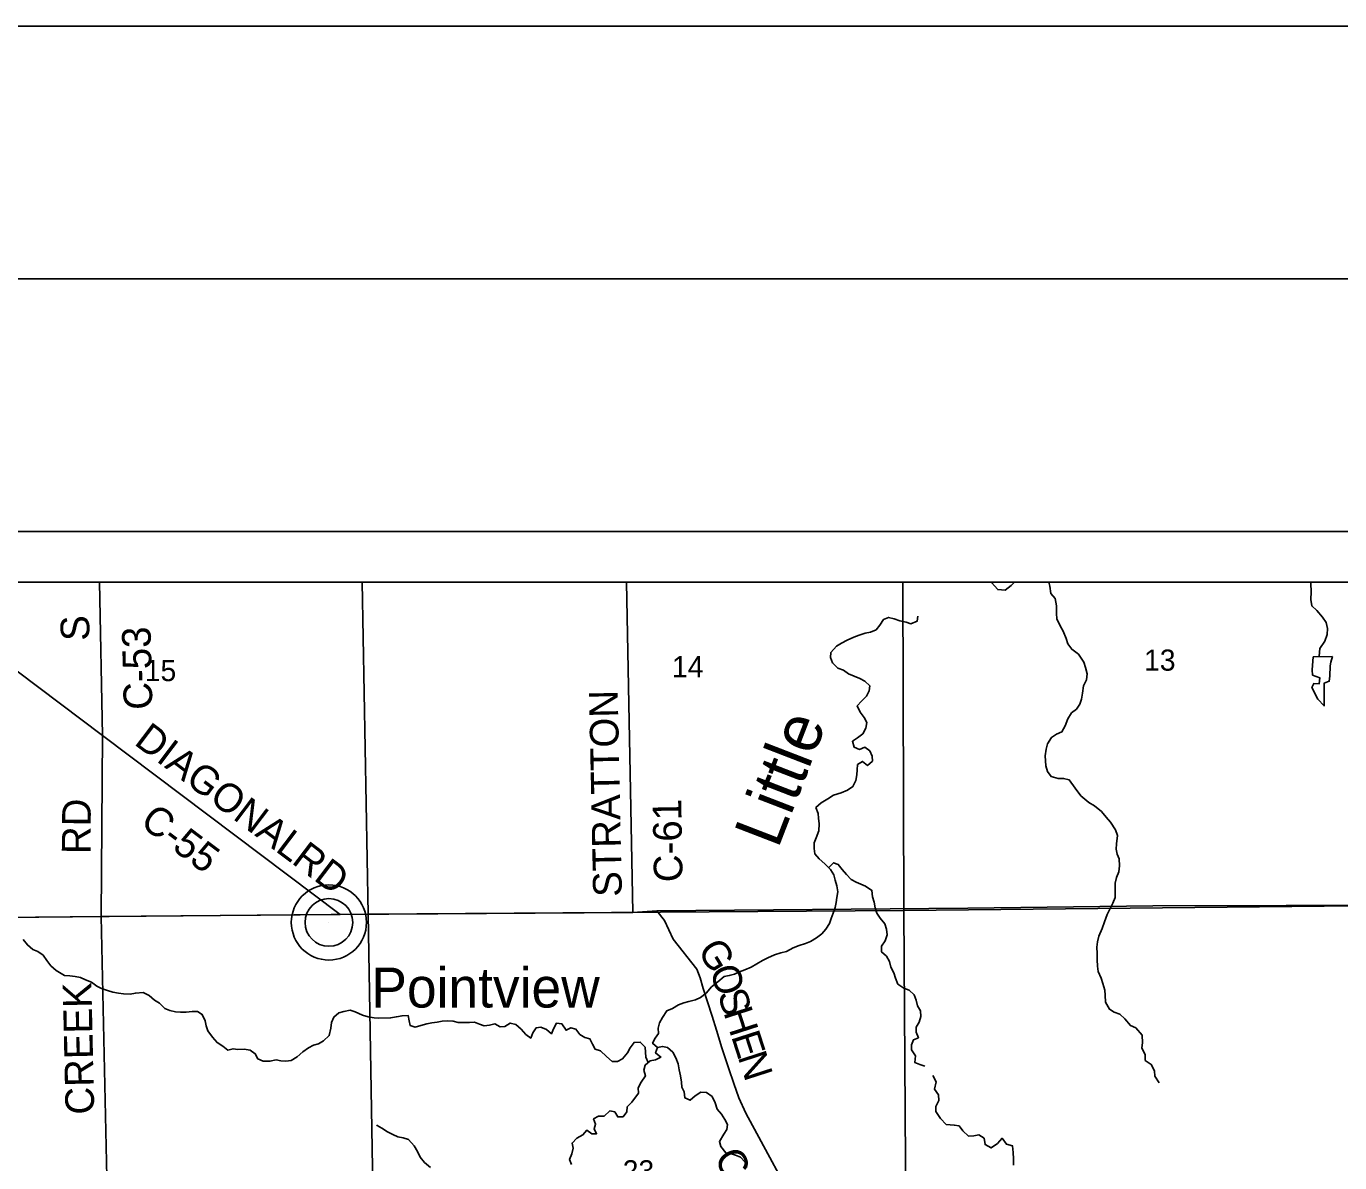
# Model space of a CAD drawing. Extents: x 0 to 34, y 0 to 22.
# Drawn here: x 2.754 to 5.353, y 19.751 to 22 of the extents above; entities that cross this region are included whole.
import ezdxf

# ---------------------------------------------------------------- set-up
doc = ezdxf.new("R2010")
doc.units = 0
for name, color, linetype in [('GM_X_County_Road', 7, 'Continuous'), ('GM_X_County_Road_Text', 7, 'Continuous'), ('GM_X_Minor_Lake', 7, 'Continuous'), ('GM_X_Minor_River', 7, 'Continuous'), ('GM_X_Minor_River_Text', 7, 'Continuous'), ('GM_X_Rail_Line', 7, 'Continuous'), ('GM_X_Section', 7, 'Continuous'), ('GM_X_Section_Text', 7, 'Continuous'), ('GM_X_State_Route', 7, 'Continuous'), ('GM_X_State_Shield', 7, 'Continuous'), ('GM_X_Township_Road', 7, 'Continuous'), ('GM_X_Township_Road_Text', 7, 'Continuous'), ('GM_X_Unincorporated', 7, 'Continuous'), ('GM_X_Unincorporated_Location', 7, 'Continuous'), ('GM_X_Unincorporated_Text', 7, 'Continuous'), ('SH_Border', 7, 'Continuous'), ('SH_Cut_Line', 7, 'Continuous'), ('SH_Data', 7, 'Continuous')]:
    doc.layers.add(name, color=color, linetype=linetype)

msp = doc.modelspace()

# ---------------------------------------------------------------- linework, layer by layer
at = {"layer": 'GM_X_County_Road'}
for p, q in [((2.9045, 20.5966), (2.8984, 20.9)), ((3.9542, 20.2462), (3.9417, 20.9)), ((2.9045, 20.5966), (3.3745, 20.2419)), ((4.0013, 20.2492), (3.9542, 20.2462))]:
    msp.add_line(p, q, dxfattribs=at)
msp.add_lwpolyline([(4.497, 19.2526), (4.4208, 19.3901), (4.2904, 19.6406), (4.1777, 19.8488), (4.1636, 19.8791), (4.1541, 19.9074), (4.1442, 19.9366), (4.1303, 19.9782), (4.1198, 20.013), (4.1112, 20.041), (4.093, 20.0955), (4.0874, 20.1167), (4.0803, 20.1337), (4.0339, 20.1931), (4.0167, 20.23), (4.0013, 20.2492)], dxfattribs=at)
at = {"layer": 'GM_X_Minor_Lake'}
for points in [[(5.3001, 20.7517), (5.2982, 20.7263), (5.2991, 20.716), (5.3137, 20.7102), (5.3123, 20.6988), (5.3013, 20.699), (5.2976, 20.6913), (5.3094, 20.6683), (5.3218, 20.6548), (5.3222, 20.7001), (5.332, 20.7036), (5.3333, 20.7135), (5.3338, 20.7341), (5.3355, 20.7417), (5.3388, 20.7524)], [(5.3388, 20.7524), (5.3001, 20.7517)]]:
    msp.add_lwpolyline(points, dxfattribs=at)
at = {"layer": 'GM_X_Minor_River'}
msp.add_line((3.4507, 20.9), (3.4509, 20.8992), dxfattribs=at)
for points in [[(4.7095, 20.9), (4.7025, 20.8932), (4.6905, 20.8842), (4.676, 20.8851), (4.6636, 20.899), (4.662, 20.9)], [(4.7773, 20.9), (4.7788, 20.8921), (4.7809, 20.8774), (4.7898, 20.8673), (4.7923, 20.8532), (4.7922, 20.838), (4.7931, 20.8274), (4.7995, 20.8135), (4.8053, 20.8029), (4.8116, 20.7886), (4.8148, 20.778), (4.8226, 20.7671), (4.8361, 20.7571), (4.8466, 20.7417), (4.8498, 20.7307), (4.8527, 20.7182), (4.8517, 20.7068), (4.8455, 20.6949), (4.8438, 20.6801), (4.8421, 20.6683), (4.8385, 20.6584), (4.8318, 20.6487), (4.8221, 20.641), (4.815, 20.6291), (4.8096, 20.6157), (4.8029, 20.6038), (4.7924, 20.5987), (4.7826, 20.5925), (4.7745, 20.5798), (4.7716, 20.5695), (4.7696, 20.5558), (4.7705, 20.5463), (4.7714, 20.5361), (4.7743, 20.5251), (4.7816, 20.5153), (4.7957, 20.511), (4.8064, 20.5112), (4.8174, 20.5083), (4.8291, 20.4922), (4.8403, 20.4772), (4.8565, 20.4634), (4.8676, 20.4571), (4.8811, 20.4459), (4.8904, 20.4347), (4.8989, 20.4246), (4.9094, 20.4099), (4.913, 20.3982), (4.911, 20.3818), (4.9104, 20.3716), (4.9125, 20.3617), (4.9161, 20.3519), (4.9167, 20.3382), (4.9154, 20.3268), (4.911, 20.3153), (4.9085, 20.3039), (4.9083, 20.2929), (4.9086, 20.2758), (4.9039, 20.2647), (4.8976, 20.2528), (4.8925, 20.2417), (4.8874, 20.2272), (4.8827, 20.2146), (4.8761, 20.1993), (4.8732, 20.1882), (4.8719, 20.1772), (4.8725, 20.165), (4.8727, 20.1525), (4.8733, 20.14), (4.875, 20.1293), (4.8809, 20.1158), (4.8841, 20.1056), (4.8881, 20.0923), (4.8887, 20.0825), (4.8893, 20.0688), (4.8971, 20.0545), (4.9067, 20.0489), (4.9174, 20.0449), (4.9274, 20.0356), (4.9386, 20.0225), (4.949, 20.0177), (4.9617, 20.0031), (4.9624, 19.9883), (4.961, 19.9784), (4.9681, 19.9645), (4.9675, 19.9534), (4.9798, 19.9453), (4.9861, 19.9325), (4.987, 19.9218), (4.9952, 19.9087)], [(5.295, 20.9), (5.2957, 20.8972), (5.296, 20.8808), (5.2955, 20.8656), (5.2976, 20.8527), (5.3076, 20.8434), (5.3189, 20.8307), (5.3259, 20.8198), (5.3284, 20.808), (5.3278, 20.7963), (5.3231, 20.7833), (5.3134, 20.7683), (5.3122, 20.7531), (5.3123, 20.7519)], [(4.518, 20.8328), (4.5165, 20.8225), (4.5041, 20.8175), (4.4946, 20.8208), (4.4825, 20.823), (4.4714, 20.8274), (4.4601, 20.83), (4.4499, 20.8261), (4.4428, 20.815), (4.4353, 20.8055), (4.4244, 20.8005), (4.4138, 20.7989), (4.4021, 20.795), (4.3911, 20.7907), (4.3779, 20.7849), (4.367, 20.7791), (4.3572, 20.7729), (4.346, 20.7607), (4.3449, 20.7504), (4.3488, 20.7402), (4.3595, 20.7293), (4.3709, 20.7256), (4.3808, 20.7184), (4.3918, 20.714), (4.4032, 20.7091), (4.4131, 20.7039), (4.4227, 20.6949), (4.4213, 20.685), (4.4164, 20.6743), (4.4067, 20.6644), (4.3981, 20.6548), (4.4035, 20.6427), (4.4115, 20.6317), (4.4169, 20.6219), (4.4151, 20.6105), (4.4092, 20.5998), (4.3986, 20.5918), (4.3885, 20.5848), (4.392, 20.5731), (4.4023, 20.5686), (4.4132, 20.5729), (4.4231, 20.5658), (4.4278, 20.5556), (4.4282, 20.5457), (4.4185, 20.5372), (4.4082, 20.5451), (4.3984, 20.5386), (4.3981, 20.5283), (4.3974, 20.5185), (4.3953, 20.507), (4.3893, 20.4952), (4.3788, 20.4879), (4.366, 20.4825), (4.3509, 20.4782), (4.3396, 20.4709), (4.3268, 20.4632), (4.3163, 20.4536), (4.3205, 20.4418), (4.3214, 20.4324), (4.3226, 20.4214), (4.322, 20.4077), (4.3168, 20.394), (4.3127, 20.384), (4.3128, 20.3727), (4.3141, 20.362), (4.3229, 20.3519), (4.3339, 20.3425), (4.3454, 20.3312), (4.3519, 20.3206), (4.3543, 20.3103), (4.3574, 20.299), (4.3594, 20.2868), (4.3573, 20.2754), (4.3562, 20.2659), (4.3544, 20.2557), (4.3504, 20.2446), (4.3467, 20.2343), (4.3434, 20.2244), (4.3359, 20.2133), (4.3277, 20.2038), (4.3175, 20.1957), (4.3058, 20.1884), (4.2957, 20.1845), (4.2828, 20.1806), (4.2715, 20.1759), (4.2579, 20.169), (4.247, 20.1659), (4.2345, 20.162), (4.2213, 20.1565), (4.2104, 20.1511), (4.1995, 20.1442), (4.1878, 20.138), (4.1754, 20.1326), (4.1652, 20.1283), (4.1554, 20.1241), (4.1448, 20.1213), (4.1346, 20.1193), (4.1218, 20.109), (4.1098, 20.0986), (4.0989, 20.0864), (4.0877, 20.0779)], [(4.3416, 20.3349), (4.351, 20.3445), (4.3605, 20.3412), (4.3685, 20.331), (4.3765, 20.3212), (4.3857, 20.311), (4.3956, 20.3061), (4.4051, 20.302), (4.4146, 20.2983), (4.4272, 20.2897), (4.4281, 20.2772), (4.4316, 20.2666), (4.4336, 20.2552), (4.4367, 20.2446), (4.4432, 20.2348), (4.4524, 20.2238), (4.4559, 20.2128), (4.4575, 20.2018), (4.4531, 20.1897), (4.446, 20.1793), (4.4461, 20.1679), (4.4556, 20.1597), (4.4618, 20.1487), (4.4646, 20.1377), (4.4707, 20.1268), (4.4735, 20.1161), (4.4785, 20.1044), (4.4899, 20.0962), (4.5009, 20.0925), (4.5109, 20.083), (4.5148, 20.0724), (4.5171, 20.0614), (4.5233, 20.0516), (4.5238, 20.0402), (4.5208, 20.0292), (4.5149, 20.0189), (4.5146, 20.0094), (4.5192, 19.998), (4.5094, 19.9942), (4.5054, 19.9839), (4.5055, 19.974), (4.5135, 19.9623), (4.5121, 19.949), (4.522, 19.9449), (4.5315, 19.9419)], [(3.0377, 20.0518), (3.0275, 20.0559), (3.0175, 20.0664), (3.0072, 20.0724), (2.9966, 20.0818), (2.9848, 20.0874), (2.9696, 20.0865), (2.959, 20.0845), (2.9458, 20.0852), (2.9363, 20.0866), (2.9246, 20.088), (2.9143, 20.0914), (2.9025, 20.0958), (2.893, 20.1003), (2.8827, 20.1078), (2.871, 20.113), (2.8611, 20.1171), (2.8504, 20.1193), (2.8398, 20.1204), (2.8292, 20.1214), (2.8125, 20.1315), (2.8022, 20.1402), (2.7941, 20.1507), (2.7868, 20.1613), (2.7765, 20.1688), (2.7667, 20.1725), (2.756, 20.1819), (2.7476, 20.1925)], [(4.0877, 20.0779), (4.0779, 20.0729), (4.065, 20.0701), (4.0548, 20.067), (4.0443, 20.0631), (4.0326, 20.0562), (4.0209, 20.0511), (4.0127, 20.0385), (4.0064, 20.0278), (4.0038, 20.0168), (4.0047, 20.0065), (3.9979, 19.997), (3.9931, 19.9871), (4.0027, 19.9788), (4.0125, 19.9808), (4.0223, 19.9786), (4.033, 19.9696), (4.0392, 19.9586), (4.0435, 19.9465), (4.0458, 19.9347), (4.0482, 19.9226), (4.0502, 19.9105), (4.0507, 19.9006), (4.0553, 19.8908), (4.057, 19.879), (4.0672, 19.8745), (4.0774, 19.883), (4.0883, 19.8907), (4.1, 19.89), (4.1107, 19.8817), (4.1169, 19.8693), (4.1211, 19.8568), (4.1292, 19.8469), (4.1357, 19.8364), (4.1415, 19.8265), (4.1401, 19.8167), (4.1341, 19.8071), (4.1252, 19.7926), (4.1279, 19.7827), (4.1379, 19.7703), (4.1473, 19.7692), (4.1568, 19.7659), (4.1671, 19.7618), (4.1759, 19.7516), (4.1798, 19.7414)], [(3.9841, 19.9491), (3.9794, 19.9596), (3.9784, 19.9794), (3.9685, 19.9895), (3.9564, 19.989), (3.9489, 19.9783), (3.9433, 19.9684), (3.9332, 19.9566), (3.9234, 19.9508), (3.9132, 19.9511), (3.9017, 19.9612), (3.8899, 19.9725), (3.8793, 19.9755), (3.8739, 19.9853), (3.8689, 19.9959), (3.859, 19.9988), (3.8491, 20.0045), (3.8414, 20.015), (3.8315, 20.018), (3.8217, 20.013), (3.8137, 20.0254), (3.8027, 20.0268), (3.7971, 20.0158), (3.7927, 20.0059), (3.7831, 20.0141), (3.7721, 20.019), (3.7623, 20.0174), (3.7559, 20.0078), (3.7519, 19.9975), (3.7419, 20.0047), (3.7331, 20.0149), (3.7221, 20.0243), (3.7114, 20.0272), (3.7009, 20.0203), (3.6911, 20.0194), (3.6808, 20.0254), (3.6706, 20.0231), (3.66, 20.0214), (3.6505, 20.0248), (3.6406, 20.0289), (3.6304, 20.028), (3.6198, 20.0283), (3.6081, 20.0286), (3.5986, 20.0308), (3.588, 20.0315), (3.5766, 20.0306), (3.5664, 20.029), (3.5562, 20.0278), (3.546, 20.0254), (3.5343, 20.0223), (3.5234, 20.0191), (3.5135, 20.0221), (3.5115, 20.0319), (3.5091, 20.0422), (3.4974, 20.0417), (3.4861, 20.0397), (3.4744, 20.0373), (3.4516, 20.0371), (3.4418, 20.0378), (3.4304, 20.0396), (3.4187, 20.0425), (3.4046, 20.0493), (3.3943, 20.0526), (3.3822, 20.0502), (3.372, 20.0475), (3.3619, 20.039), (3.3578, 20.0283), (3.3561, 20.0169), (3.3532, 20.0025), (3.3415, 19.9917), (3.3317, 19.986), (3.3219, 19.9836), (3.3121, 19.9782), (3.3008, 19.9705), (3.2896, 19.9605), (3.2775, 19.9532), (3.2673, 19.952), (3.2575, 19.9527), (3.248, 19.9541), (3.2359, 19.9517), (3.2226, 19.9516), (3.2116, 19.9564), (3.2066, 19.9663), (3.1967, 19.9734), (3.1846, 19.9756), (3.1724, 19.9751), (3.163, 19.9762), (3.1524, 19.9738), (3.1425, 19.9813), (3.1311, 19.9884), (3.1223, 19.9994), (3.1131, 20.0118), (3.1095, 20.022), (3.1079, 20.0319), (3.1018, 20.0444), (3.0923, 20.05), (3.082, 20.0503), (3.0699, 20.049), (3.0589, 20.0489), (3.0491, 20.0496), (3.0377, 20.0518)], [(4.0027, 19.9788), (3.999, 19.9681), (4.0096, 19.9599), (3.9987, 19.9541), (3.9881, 19.9525), (3.978, 19.944), (3.9758, 19.9341), (3.9789, 19.9228), (3.9704, 19.9102), (3.9648, 19.8987), (3.9653, 19.8881), (3.9522, 19.8709), (3.9428, 19.8613), (3.9421, 19.8514), (3.9346, 19.8415), (3.924, 19.8414), (3.9183, 19.8516), (3.9084, 19.8534), (3.8975, 19.8431), (3.8862, 19.843), (3.8764, 19.8376), (3.8803, 19.8273), (3.8773, 19.8178), (3.8823, 19.808), (3.8725, 19.8079), (3.863, 19.8154), (3.8551, 19.8059), (3.843, 19.7993), (3.8337, 19.7897), (3.8357, 19.7795), (3.8335, 19.7685), (3.8287, 19.757), (3.8326, 19.7472)], [(4.7071, 19.7459), (4.7073, 19.7584), (4.7063, 19.771), (4.705, 19.7842), (4.6932, 19.7878), (4.6846, 19.7991), (4.6753, 19.7887), (4.6629, 19.7801), (4.651, 19.7868), (4.6489, 19.7993), (4.6389, 19.8059), (4.6287, 19.8039), (4.6185, 19.803), (4.6069, 19.8138), (4.5996, 19.8235), (4.59, 19.8253), (4.5741, 19.8265), (4.5625, 19.8385), (4.5535, 19.8524), (4.5534, 19.8623), (4.5592, 19.8742), (4.5587, 19.8848), (4.5509, 19.8965), (4.5541, 19.9106), (4.5474, 19.9234)], [(3.5532, 19.7414), (3.5418, 19.7515), (3.533, 19.7617), (3.5276, 19.7727), (3.521, 19.7844), (3.5099, 19.7968), (3.4993, 19.7998), (3.4887, 19.8023), (3.4792, 19.8068), (3.4685, 19.8117), (3.4575, 19.8192), (3.4479, 19.8244), (3.4476, 19.8255)]]:
    msp.add_lwpolyline(points, dxfattribs=at)
at = {"layer": 'GM_X_Rail_Line'}
msp.add_lwpolyline([(5.523, 19.2739), (5.5102, 20.2613), (5.4984, 20.9), (2.1, 20.9)], dxfattribs=at)
at = {"layer": 'GM_X_Section'}
for points in [[(4.4904, 20.2497), (4.497, 19.2557), (3.4475, 19.2384), (3.4305, 20.2427)], [(3.4305, 20.2427), (3.4475, 19.2384), (2.4219, 19.2256), (2.4052, 20.2337)]]:
    msp.add_lwpolyline(points, close=True, dxfattribs=at)
at = {"layer": 'GM_X_State_Route'}
msp.add_line((3.9542, 20.2462), (4.0013, 20.2492), dxfattribs=at)
for points in [[(4.0013, 20.2492), (4.6171, 20.2548), (4.9829, 20.2595), (5.5104, 20.2608)], [(2.1, 20.2294), (2.9018, 20.2384), (3.3745, 20.2419), (3.9542, 20.2462)]]:
    msp.add_lwpolyline(points, dxfattribs=at)
at = {"layer": 'GM_X_State_Shield'}
for points in [[(3.4184, 20.9), (2.3919, 20.9), (2.4052, 20.2337), (3.4305, 20.2427)], [(4.4883, 20.9), (3.4184, 20.9), (3.4305, 20.2427), (4.4904, 20.2497)], [(5.5067, 20.9), (4.4883, 20.9), (4.4904, 20.2497), (5.514, 20.2608)]]:
    msp.add_lwpolyline(points, close=True, dxfattribs=at)
at = {"layer": 'GM_X_Township_Road'}
for p, q in [((2.5009, 20.9), (2.9045, 20.5966)), ((2.9018, 20.2384), (2.9045, 20.5966)), ((2.9238, 19.2285), (2.9018, 20.2384))]:
    msp.add_line(p, q, dxfattribs=at)
at = {"layer": 'GM_X_Unincorporated'}
for radius in [0.0744, 0.0472]:
    msp.add_circle((3.3525, 20.2263), radius, dxfattribs=at)
at = {"layer": 'GM_X_Unincorporated_Location'}
msp.add_line((3.3525, 20.2263), (3.3525, 20.2263), dxfattribs=at)
at = {"layer": 'SH_Border'}
msp.add_lwpolyline([(1.5, 21.5), (33.5, 21.5), (33.5, 0.5), (1.5, 0.5)], close=True, dxfattribs=at)
at = {"layer": 'SH_Cut_Line'}
msp.add_lwpolyline([(0, 0), (34, 0), (34, 22), (0, 22)], close=True, dxfattribs=at)
msp.add_lwpolyline([(8.9, 20.9), (2.1, 20.9)], dxfattribs=at)
at = {"layer": 'SH_Data'}
for p, q in [((2, 21), (9, 21)), ((2.1, 20.9), (8.9, 20.9))]:
    msp.add_line(p, q, dxfattribs=at)

# ---------------------------------------------------------------- texts
at = {"layer": 'GM_X_County_Road_Text'}
for s, height, rotation, p in [('S', 0.0568, 91.2447, (2.879, 20.7841)), ('C-53', 0.05682, 91.3727, (3.0034, 20.6478)), ('STRATTON', 0.05682, 91.1851, (3.9324, 20.2775)), ('DIAGONAL', 0.05682, 322.9476, (2.9649, 20.5799)), ('C-61', 0.05682, 91.0299, (4.0526, 20.3064)), ('C-55', 0.05682, 323.061, (2.9762, 20.4198)), ('RD', 0.05682, 322.7338, (3.2766, 20.3449)), ('G', 0.0568, 301.4486, (4.0805, 20.172)), ('O', 0.0568, 288.5202, (4.1052, 20.1324)), ('S', 0.0568, 287.8783, (4.121, 20.0852)), ('H', 0.0568, 287.8682, (4.1328, 20.0487)), ('E', 0.0568, 287.8713, (4.1481, 20.0011)), ('N', 0.0568, 287.8722, (4.1612, 19.9606)), ('C-61', 0.05682, 298.2551, (4.1136, 19.7612))]:
    msp.add_text(s, height=height, rotation=rotation, dxfattribs=at).set_placement(p)
at = {"layer": 'GM_X_Minor_River_Text'}
msp.add_text('Little', height=0.09475, rotation=68.8906, dxfattribs=at).set_placement((4.241, 20.3704))
at = {"layer": 'GM_X_Section_Text'}
for s, p in [('15', (2.9881, 20.7039)), ('14', (4.0314, 20.7116)), ('13', (4.9656, 20.7246)), ('23', (3.9339, 19.7138))]:
    msp.add_text(s, height=0.04186, rotation=0, dxfattribs=at).set_placement(p)
at = {"layer": 'GM_X_Township_Road_Text'}
for s, rotation, p in [('RD', 89.5063, (2.8807, 20.3614)), ('CREEK', 91.2592, (2.8882, 19.8466))]:
    msp.add_text(s, height=0.05682, rotation=rotation, dxfattribs=at).set_placement(p)
at = {"layer": 'GM_X_Unincorporated_Text'}
msp.add_text('Pointview', height=0.07898, rotation=0, dxfattribs=at).set_placement((3.4364, 20.0579))

doc.saveas('drawing.dxf')
